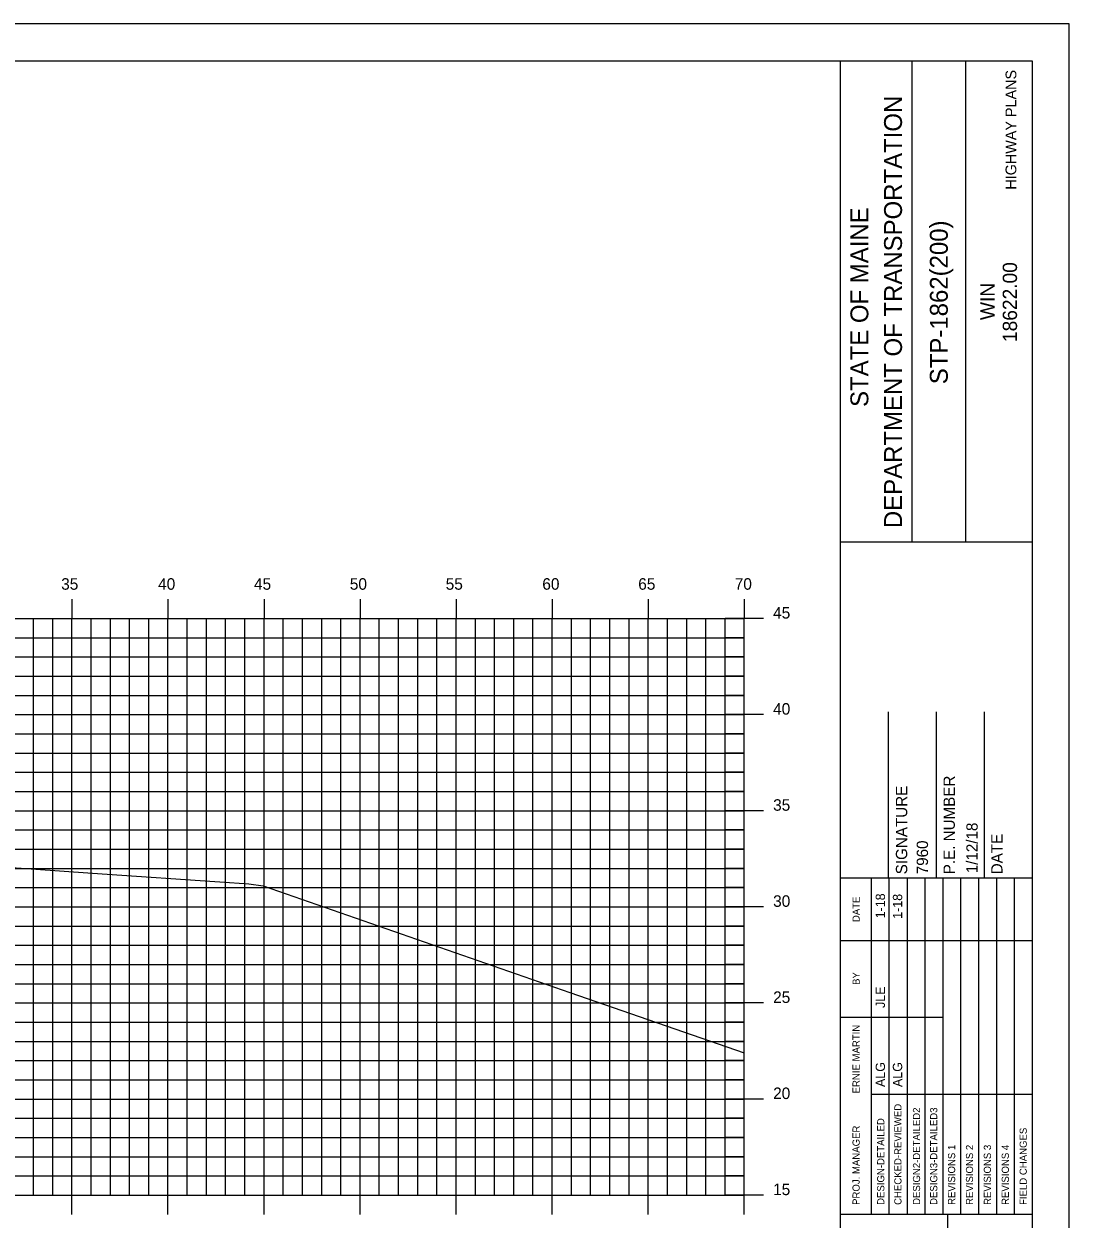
# Model space of a CAD drawing. Extents: x 1037709 to 1037879, y 394883 to 394993.
# Drawn here: x 1037824.7 to 1037879.1, y 394930.4 to 394992.6 of the extents above; entities that cross this region are included whole.
import ezdxf

# ---------------------------------------------------------------- set-up
doc = ezdxf.new("R2010")
doc.units = 0
for name, color, linetype in [('BORDER', 7, 'Continuous'), ('H_V ANNOTATION', 7, 'Continuous'), ('HIGHWAY_TITLE', 7, 'Continuous'), ('MAJOR', 7, 'Continuous'), ('MINOR', 7, 'Continuous'), ('PLOT BOUNDARY', 7, 'Continuous'), ('S_Roadway_Centerline', 7, 'Continuous')]:
    doc.layers.add(name, color=color, linetype=linetype)

msp = doc.modelspace()

# ---------------------------------------------------------------- linework, layer by layer
at = {"layer": 'BORDER'}
for p, q in [((1037877.157, 394990.686), (1037717.157, 394990.686)), ((1037867.157, 394885.686), (1037867.157, 394990.689)), ((1037870.886, 394965.683), (1037870.886, 394990.683)), ((1037873.681, 394965.683), (1037873.681, 394990.683)), ((1037877.157, 394885.686), (1037877.157, 394990.686)), ((1037867.158, 394965.68), (1037877.157, 394965.68)), ((1037869.657, 394948.189), (1037869.657, 394956.836)), ((1037872.157, 394948.189), (1037872.157, 394956.836)), ((1037874.657, 394948.189), (1037874.657, 394956.836)), ((1037867.157, 394948.189), (1037877.157, 394948.189)), ((1037867.157, 394930.689), (1037877.157, 394930.689)), ((1037872.748, 394895.689), (1037872.748, 394930.689))]:
    msp.add_line(p, q, dxfattribs=at)
for points in [[(1037868.772, 394944.939), (1037868.772, 394948.189)], [(1037869.705, 394930.692), (1037869.705, 394948.189)], [(1037870.636, 394948.189), (1037870.636, 394930.692)], [(1037871.568, 394930.692), (1037871.568, 394948.189)], [(1037872.5, 394930.692), (1037872.5, 394948.189)], [(1037873.431, 394930.692), (1037873.431, 394948.189)], [(1037874.363, 394930.692), (1037874.363, 394948.189)], [(1037875.295, 394930.692), (1037875.295, 394948.189)], [(1037876.226, 394930.692), (1037876.226, 394948.189)], [(1037868.773, 394930.692), (1037868.773, 394947.483)], [(1037867.157, 394944.939), (1037877.157, 394944.939)], [(1037867.157, 394940.939), (1037868.773, 394940.939)], [(1037868.772, 394940.939), (1037872.499, 394940.939)], [(1037868.772, 394936.939), (1037877.157, 394936.939)]]:
    msp.add_lwpolyline(points, dxfattribs=at)
at = {"layer": 'MAJOR'}
for p, q in [((1037827.157, 394962.688), (1037827.157, 394961.686)), ((1037832.157, 394962.688), (1037832.157, 394961.686)), ((1037837.157, 394962.688), (1037837.157, 394961.686)), ((1037842.157, 394962.688), (1037842.157, 394961.686)), ((1037847.157, 394962.688), (1037847.157, 394961.686)), ((1037852.157, 394962.688), (1037852.157, 394961.686)), ((1037857.157, 394962.688), (1037857.157, 394961.686)), ((1037862.157, 394962.688), (1037862.157, 394961.686)), ((1037722.157, 394961.686), (1037862.157, 394961.686)), ((1037827.157, 394931.686), (1037827.157, 394961.686)), ((1037832.157, 394931.686), (1037832.157, 394961.686)), ((1037837.157, 394931.686), (1037837.157, 394961.686)), ((1037842.157, 394931.686), (1037842.157, 394961.686)), ((1037847.157, 394931.686), (1037847.157, 394961.686)), ((1037852.157, 394931.686), (1037852.157, 394961.686)), ((1037857.157, 394931.686), (1037857.157, 394961.686)), ((1037863.159, 394961.686), (1037861.155, 394961.686)), ((1037862.157, 394931.686), (1037862.157, 394961.686)), ((1037722.157, 394956.686), (1037862.157, 394956.686)), ((1037863.159, 394956.686), (1037861.155, 394956.686)), ((1037722.157, 394951.686), (1037862.157, 394951.686)), ((1037863.159, 394951.686), (1037861.155, 394951.686)), ((1037722.157, 394946.686), (1037862.157, 394946.686)), ((1037863.159, 394946.686), (1037861.155, 394946.686)), ((1037722.157, 394941.686), (1037862.157, 394941.686)), ((1037863.159, 394941.686), (1037861.155, 394941.686)), ((1037722.157, 394936.686), (1037862.157, 394936.686)), ((1037863.159, 394936.686), (1037861.155, 394936.686)), ((1037722.157, 394931.686), (1037862.157, 394931.686)), ((1037827.157, 394930.684), (1037827.157, 394931.686)), ((1037832.157, 394930.684), (1037832.157, 394931.686)), ((1037837.157, 394930.684), (1037837.157, 394931.686)), ((1037842.157, 394930.684), (1037842.157, 394931.686)), ((1037847.157, 394930.684), (1037847.157, 394931.686)), ((1037852.157, 394930.684), (1037852.157, 394931.686)), ((1037857.157, 394930.684), (1037857.157, 394931.686)), ((1037863.159, 394931.686), (1037861.155, 394931.686)), ((1037862.157, 394930.684), (1037862.157, 394931.686))]:
    msp.add_line(p, q, dxfattribs=at)
at = {"layer": 'MINOR'}
for p, q in [((1037825.157, 394931.686), (1037825.157, 394961.686)), ((1037826.157, 394931.686), (1037826.157, 394961.686)), ((1037828.157, 394931.686), (1037828.157, 394961.686)), ((1037829.157, 394931.686), (1037829.157, 394961.686)), ((1037830.157, 394931.686), (1037830.157, 394961.686)), ((1037831.157, 394931.686), (1037831.157, 394961.686)), ((1037833.157, 394931.686), (1037833.157, 394961.686)), ((1037834.157, 394931.686), (1037834.157, 394961.686)), ((1037835.157, 394931.686), (1037835.157, 394961.686)), ((1037836.157, 394931.686), (1037836.157, 394961.686)), ((1037838.157, 394931.686), (1037838.157, 394961.686)), ((1037839.157, 394931.686), (1037839.157, 394961.686)), ((1037840.157, 394931.686), (1037840.157, 394961.686)), ((1037841.157, 394931.686), (1037841.157, 394961.686)), ((1037843.157, 394931.686), (1037843.157, 394961.686)), ((1037844.157, 394931.686), (1037844.157, 394961.686)), ((1037845.157, 394931.686), (1037845.157, 394961.686)), ((1037846.157, 394931.686), (1037846.157, 394961.686)), ((1037848.157, 394931.686), (1037848.157, 394961.686)), ((1037849.157, 394931.686), (1037849.157, 394961.686)), ((1037850.157, 394931.686), (1037850.157, 394961.686)), ((1037851.157, 394931.686), (1037851.157, 394961.686)), ((1037853.157, 394931.686), (1037853.157, 394961.686)), ((1037854.157, 394931.686), (1037854.157, 394961.686)), ((1037855.157, 394931.686), (1037855.157, 394961.686)), ((1037856.157, 394931.686), (1037856.157, 394961.686)), ((1037858.157, 394931.686), (1037858.157, 394961.686)), ((1037859.157, 394931.686), (1037859.157, 394961.686)), ((1037860.157, 394931.686), (1037860.157, 394961.686)), ((1037861.157, 394931.686), (1037861.157, 394961.686)), ((1037722.157, 394960.686), (1037862.157, 394960.686)), ((1037862.157, 394960.686), (1037861.155, 394960.686)), ((1037722.157, 394959.686), (1037862.157, 394959.686)), ((1037862.157, 394959.686), (1037861.155, 394959.686)), ((1037722.157, 394958.686), (1037862.157, 394958.686)), ((1037862.157, 394958.686), (1037861.155, 394958.686)), ((1037722.157, 394957.686), (1037862.157, 394957.686)), ((1037862.157, 394957.686), (1037861.155, 394957.686)), ((1037722.157, 394955.686), (1037862.157, 394955.686)), ((1037862.157, 394955.686), (1037861.155, 394955.686)), ((1037722.157, 394954.686), (1037862.157, 394954.686)), ((1037862.157, 394954.686), (1037861.155, 394954.686)), ((1037722.157, 394953.686), (1037862.157, 394953.686)), ((1037862.157, 394953.686), (1037861.155, 394953.686)), ((1037722.157, 394952.686), (1037862.157, 394952.686)), ((1037862.157, 394952.686), (1037861.155, 394952.686)), ((1037722.157, 394950.686), (1037862.157, 394950.686)), ((1037862.157, 394950.686), (1037861.155, 394950.686)), ((1037722.157, 394949.686), (1037862.157, 394949.686)), ((1037862.157, 394949.686), (1037861.155, 394949.686)), ((1037722.157, 394948.686), (1037862.157, 394948.686)), ((1037862.157, 394948.686), (1037861.155, 394948.686)), ((1037722.157, 394947.686), (1037862.157, 394947.686)), ((1037862.157, 394947.686), (1037861.155, 394947.686)), ((1037722.157, 394945.686), (1037862.157, 394945.686)), ((1037862.157, 394945.686), (1037861.155, 394945.686)), ((1037722.157, 394944.686), (1037862.157, 394944.686)), ((1037862.157, 394944.686), (1037861.155, 394944.686)), ((1037722.157, 394943.686), (1037862.157, 394943.686)), ((1037862.157, 394943.686), (1037861.155, 394943.686)), ((1037722.157, 394942.686), (1037862.157, 394942.686)), ((1037862.157, 394942.686), (1037861.155, 394942.686)), ((1037722.157, 394940.686), (1037862.157, 394940.686)), ((1037862.157, 394940.686), (1037861.155, 394940.686)), ((1037722.157, 394939.686), (1037862.157, 394939.686)), ((1037862.157, 394939.686), (1037861.155, 394939.686)), ((1037722.157, 394938.686), (1037862.157, 394938.686)), ((1037862.157, 394938.686), (1037861.155, 394938.686)), ((1037722.157, 394937.686), (1037862.157, 394937.686)), ((1037862.157, 394937.686), (1037861.155, 394937.686)), ((1037722.157, 394935.686), (1037862.157, 394935.686)), ((1037862.157, 394935.686), (1037861.155, 394935.686)), ((1037722.157, 394934.686), (1037862.157, 394934.686)), ((1037862.157, 394934.686), (1037861.155, 394934.686)), ((1037722.157, 394933.686), (1037862.157, 394933.686)), ((1037862.157, 394933.686), (1037861.155, 394933.686)), ((1037722.157, 394932.686), (1037862.157, 394932.686)), ((1037862.157, 394932.686), (1037861.155, 394932.686))]:
    msp.add_line(p, q, dxfattribs=at)
at = {"layer": 'PLOT BOUNDARY'}
msp.add_lwpolyline([(1037709.064, 394882.627), (1037879.064, 394882.627), (1037879.064, 394992.627), (1037709.064, 394992.627)], close=True, dxfattribs=at)
at = {"layer": 'S_Roadway_Centerline'}
msp.add_lwpolyline([(1037824.001, 394948.742), (1037825.028, 394948.664), (1037828.223, 394948.444), (1037835.355, 394947.959), (1037836.368, 394947.883), (1037837.11, 394947.787), (1037853.074, 394942.235), (1037862.157, 394939.083)], dxfattribs=at)

# ---------------------------------------------------------------- texts
at = {"layer": 'BORDER'}
for s, height, p in [('DEPARTMENT OF TRANSPORTATION', 0.93176, (1037870.364, 394966.392)), ('STATE OF MAINE', 0.93176, (1037868.612, 394972.698)), ('STP-1862(200)', 0.93176, (1037872.749, 394973.88)), ('18622.00', 0.7453, (1037876.353, 394976.073)), ('WIN', 0.7453, (1037875.194, 394977.216)), ('P.E. NUMBER', 0.59055, (1037873.118, 394948.381)), ('SIGNATURE', 0.5906, (1037870.638, 394948.381)), ('1/12/18', 0.5906, (1037874.305, 394948.433)), ('DATE', 0.5906, (1037875.598, 394948.381)), ('7960', 0.5906, (1037871.72, 394948.381)), ('DATE', 0.3714, (1037868.161, 394945.895)), ('1-18', 0.4845, (1037869.48, 394946.087)), ('1-18', 0.4845, (1037870.374, 394946.064)), ('BY', 0.3714, (1037868.161, 394942.624)), ('JLE', 0.4845, (1037869.48, 394941.424)), ('ERNIE MARTIN', 0.37275, (1037868.161, 394936.98)), ('ALG', 0.4845, (1037869.48, 394937.312)), ('ALG', 0.4845, (1037870.374, 394937.312)), ('CHECKED-REVIEWED', 0.37275, (1037870.338, 394931.177)), ('DESIGN2-DETAILED2', 0.37275, (1037871.307, 394931.177)), ('DESIGN3-DETAILED3', 0.37275, (1037872.201, 394931.177)), ('DESIGN-DETAILED', 0.37275, (1037869.444, 394931.177)), ('PROJ. MANAGER', 0.37275, (1037868.161, 394931.177)), ('FIELD CHANGES', 0.37275, (1037876.86, 394931.177)), ('REVISIONS 1', 0.37275, (1037873.133, 394931.177)), ('REVISIONS 2', 0.37275, (1037874.065, 394931.177)), ('REVISIONS 3', 0.37275, (1037874.996, 394931.177)), ('REVISIONS 4', 0.37275, (1037875.928, 394931.177))]:
    msp.add_text(s, height=height, rotation=90, dxfattribs=at).set_placement(p)
at = {"layer": 'H_V ANNOTATION'}
for s, p in [('35', (1037826.598, 394963.186)), ('40', (1037831.643, 394963.186)), ('45', (1037836.635, 394963.186)), ('50', (1037841.622, 394963.186)), ('55', (1037846.614, 394963.186)), ('60', (1037851.643, 394963.186)), ('65', (1037856.635, 394963.186)), ('70', (1037861.659, 394963.186)), ('45', (1037863.657, 394961.686)), ('40', (1037863.657, 394956.686)), ('35', (1037863.657, 394951.686)), ('30', (1037863.657, 394946.686)), ('25', (1037863.657, 394941.686)), ('20', (1037863.657, 394936.686)), ('15', (1037863.657, 394931.686))]:
    msp.add_text(s, height=0.6, dxfattribs=at).set_placement(p)
at = {"layer": 'HIGHWAY_TITLE'}
msp.add_text('HIGHWAY PLANS', height=0.55901, rotation=90, dxfattribs=at).set_placement((1037876.315, 394984.001))

doc.saveas('drawing.dxf')
